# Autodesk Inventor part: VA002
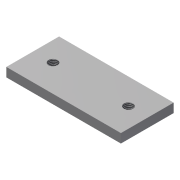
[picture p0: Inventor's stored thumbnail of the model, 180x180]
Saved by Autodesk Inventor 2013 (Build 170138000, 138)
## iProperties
Manager: P MOLLOY
Company: NUIG
Shininess: 64.0
Length Units: 11269
Angle Units: 11279
Time Units: 11290
Mass Units: 11283
Length Display Precision: 3
Angle Display Precision: 2
Compacted: True
Part Number: VA002
Document SubType Name: Modeling
Created: 2004-12
Designer: warren davies
Manufacturer: Standard
Standards Organization: Custom
Material: Galvanized Steel
Mass: 122.623 g
Surface Area: 67.651 cm^2
Volume: 15.6207 cm^3
Density: 7.85 g/cm^3
Density: 0.0
Volumn: 0.0
Area: 0.0
PropertySet Name: Model Information
Control State: 0
Master: False
Checked Out: False
Title: JAWFACE
Subject: VICE ASSEMBLY
Author: warren davies
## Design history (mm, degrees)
sketch "Sketch1"
  geometry: L1 (1.899, 2.037)-(77.899, 2.037); L2 (77.899, 2.037)-(77.899, -32.963); L3 (77.899, -32.963)-(1.899, -32.963); L4 (1.899, -32.963)-(1.899, 2.037); C1 r 3 at (14.899, -14.963); C2 r 3 at (64.899, -14.963)
  constraints: 8 end point, 2 centre point, 2 parallel, 1 equal radius, 1 horizontal, 1 horizontal alignment, 1 perpendicular
  dimensions: "d0" = 76 distance of L1.start L1.end; "d1" = 35 distance of L3.end L1.start; "d2" = 6 diameter of C1; "d3" = 50 distance of C2.centre C1.centre; "d4" = 13 distance from line of L2 C2.centre; "d5" = 18 distance from line of L3 C2.centre
extrude "Extrusion1" new body sketch "Sketch1" distance "d6" = 6; taper "d7" = 0 deg
thread "Thread1" dims "d8" = 10, "d9" = 0
thread "Thread2" dims "d10" = 10, "d11" = 0
body "Solid1"
